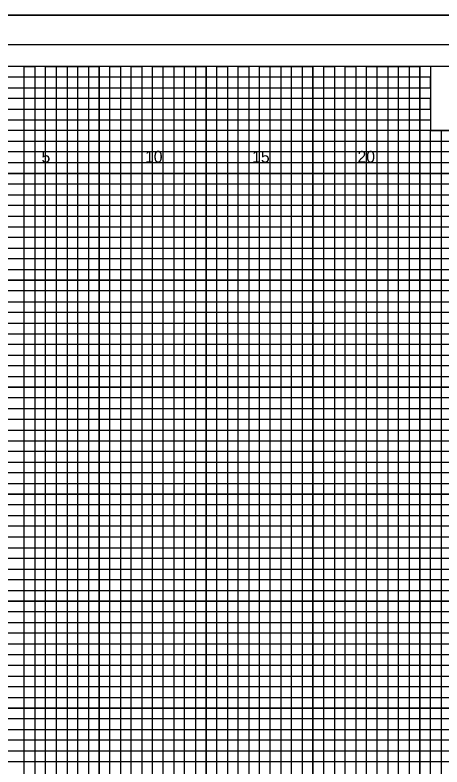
# Model space of a CAD drawing. Extents: x -4 to 103, y -2 to 67.
# Drawn here: x 54.82 to 74.78, y 32.25 to 67.4 of the extents above; entities that cross this region are included whole.
import ezdxf

# ---------------------------------------------------------------- set-up
doc = ezdxf.new("R2010")
doc.units = 0
for name, color, linetype in [('Exist XS Ground Line', 7, 'Continuous'), ('Old_Level_10', 7, 'Continuous'), ('Old_Level_16', 7, 'Continuous'), ('Old_Level_3', 7, 'Continuous'), ('Old_Level_4', 7, 'Continuous'), ('Old_Level_5', 7, 'Continuous'), ('Old_Level_8', 7, 'Continuous'), ('Prop XS Elevation Labels', 7, 'Continuous')]:
    doc.layers.add(name, color=color, linetype=linetype)

msp = doc.modelspace()

# ---------------------------------------------------------------- linework, layer by layer
at = {"layer": 'Exist XS Ground Line'}
for points in [[(102.5, 65), (0, 65), (0, 0), (102.5, 0)], [(83.75, 65), (74.25, 65), (74.25, 62), (83.75, 62)]]:
    msp.add_lwpolyline(points, close=True, dxfattribs=at)
at = {"layer": 'Old_Level_10'}
for p, q in [((56.25, 0), (56.25, 65)), ((58.75, 0), (58.75, 65)), ((61.25, 0), (61.25, 65)), ((63.75, 0), (63.75, 65)), ((66.25, 0), (66.25, 65)), ((68.75, 0), (68.75, 65)), ((71.25, 0), (71.25, 65)), ((73.75, 0), (73.75, 65)), ((0, 62.5), (74.25, 62.5)), ((0, 60), (102.5, 60)), ((0, 57.5), (102.5, 57.5)), ((0, 55), (102.5, 55)), ((0, 52.5), (102.5, 52.5)), ((0, 50), (102.5, 50)), ((0, 47.5), (102.5, 47.5)), ((0, 45), (102.5, 45)), ((0, 42.5), (102.5, 42.5)), ((0, 40), (102.5, 40)), ((0, 37.5), (102.5, 37.5)), ((0, 35), (102.5, 35)), ((0, 32.5), (102.5, 32.5))]:
    msp.add_line(p, q, dxfattribs=at)
at = {"layer": 'Old_Level_3'}
msp.add_line((-3.5, 67.4), (103.4, 67.4), dxfattribs=at)
at = {"layer": 'Old_Level_4'}
msp.add_lwpolyline([(103, 66), (-2.8, 66), (-2.8, -1), (103, -1)], close=True, dxfattribs=at)
at = {"layer": 'Old_Level_5'}
msp.add_lwpolyline([(103.4, 67.4), (-3.5, 67.4), (-3.5, -2.425), (103.4, -2.425)], close=True, dxfattribs=at)
at = {"layer": 'Old_Level_8'}
for points in [[(56.25, 0), (56.25, 65), (58.75, 65), (58.75, 0)], [(61.25, 0), (61.25, 65), (63.75, 65), (63.75, 0)], [(66.25, 0), (66.25, 65), (68.75, 65), (68.75, 0)], [(71.25, 0), (71.25, 65), (73.75, 65), (73.75, 0)], [(0, 62.5), (74.25, 62.5)], [(0, 57.5), (102.5, 57.5), (102.5, 60), (0, 60)], [(0, 52.5), (102.5, 52.5), (102.5, 55), (0, 55)], [(0, 47.5), (102.5, 47.5), (102.5, 50), (0, 50)], [(0, 42.5), (102.5, 42.5), (102.5, 45), (0, 45)], [(0, 37.5), (102.5, 37.5), (102.5, 40), (0, 40)], [(0, 32.5), (102.5, 32.5), (102.5, 35), (0, 35)]]:
    msp.add_lwpolyline(points, dxfattribs=at)
at = {"layer": 'Prop XS Elevation Labels'}
for points in [[(55.25, 0), (55.25, 65), (55.75, 65), (55.75, 0)], [(56.75, 0), (56.75, 65), (57.25, 65), (57.25, 0)], [(57.75, 0), (57.75, 65), (58.25, 65), (58.25, 0)], [(59.25, 0), (59.25, 65), (59.75, 65), (59.75, 0)], [(60.25, 0), (60.25, 65), (60.75, 65), (60.75, 0)], [(61.75, 0), (61.75, 65), (62.25, 65), (62.25, 0)], [(62.75, 0), (62.75, 65), (63.25, 65), (63.25, 0)], [(64.25, 0), (64.25, 65), (64.75, 65), (64.75, 0)], [(65.25, 0), (65.25, 65), (65.75, 65), (65.75, 0)], [(66.75, 0), (66.75, 65), (67.25, 65), (67.25, 0)], [(67.75, 0), (67.75, 65), (68.25, 65), (68.25, 0)], [(69.25, 0), (69.25, 65)], [(69.25, 65), (69.75, 65), (69.75, 0)], [(70.25, 0), (70.25, 65), (70.75, 65), (70.75, 0)], [(71.75, 0), (71.75, 65), (72.25, 65), (72.25, 0)], [(72.75, 0), (72.75, 65), (73.25, 65), (73.25, 0)], [(0, 62), (0, 63), (74.25, 63), (74.25, 63.5), (0, 63.5), (0, 64), (74.25, 64), (74.25, 64.5), (0, 64.5)], [(0, 61.5), (102.5, 61.5), (102.5, 62), (0, 62)], [(74.25, 0), (74.25, 62), (74.75, 62), (74.75, 0)], [(0, 60.5), (102.5, 60.5), (102.5, 61), (0, 61)], [(0, 59), (102.5, 59), (102.5, 59.5), (0, 59.5)], [(0, 58), (102.5, 58), (102.5, 58.5), (0, 58.5)], [(0, 56.5), (102.5, 56.5), (102.5, 57), (0, 57)], [(0, 55.5), (102.5, 55.5), (102.5, 56), (0, 56)], [(0, 54), (102.5, 54), (102.5, 54.5), (0, 54.5)], [(0, 53), (102.5, 53), (102.5, 53.5), (0, 53.5)], [(0, 51.5), (102.5, 51.5), (102.5, 52), (0, 52)], [(0, 50.5), (102.5, 50.5), (102.5, 51), (0, 51)], [(0, 49), (102.5, 49), (102.5, 49.5), (0, 49.5)], [(0, 48), (102.5, 48), (102.5, 48.5), (0, 48.5)], [(0, 46.5), (102.5, 46.5), (102.5, 47), (0, 47)], [(0, 45.5), (102.5, 45.5), (102.5, 46), (0, 46)], [(0, 44), (102.5, 44), (102.5, 44.5), (0, 44.5)], [(0, 43), (102.5, 43), (102.5, 43.5), (0, 43.5)], [(0, 41.5), (102.5, 41.5), (102.5, 42), (0, 42)], [(0, 40.5), (102.5, 40.5), (102.5, 41), (0, 41)], [(0, 39), (102.5, 39), (102.5, 39.5), (0, 39.5)], [(0, 38), (102.5, 38), (102.5, 38.5), (0, 38.5)], [(0, 36.5), (102.5, 36.5), (102.5, 37), (0, 37)], [(0, 35.5), (102.5, 35.5), (102.5, 36), (0, 36)], [(0, 34), (102.5, 34), (102.5, 34.5), (0, 34.5)], [(0, 33), (102.5, 33), (102.5, 33.5), (0, 33.5)]]:
    msp.add_lwpolyline(points, dxfattribs=at)

# ---------------------------------------------------------------- texts
at = {"layer": 'Old_Level_16'}
for s, p in [('5', (56.0574, 60.5)), ('10', (60.8971, 60.5)), ('15', (65.9057, 60.5)), ('20', (70.8312, 60.5))]:
    msp.add_text(s, height=0.55, dxfattribs=at).set_placement(p)

doc.saveas('drawing.dxf')
